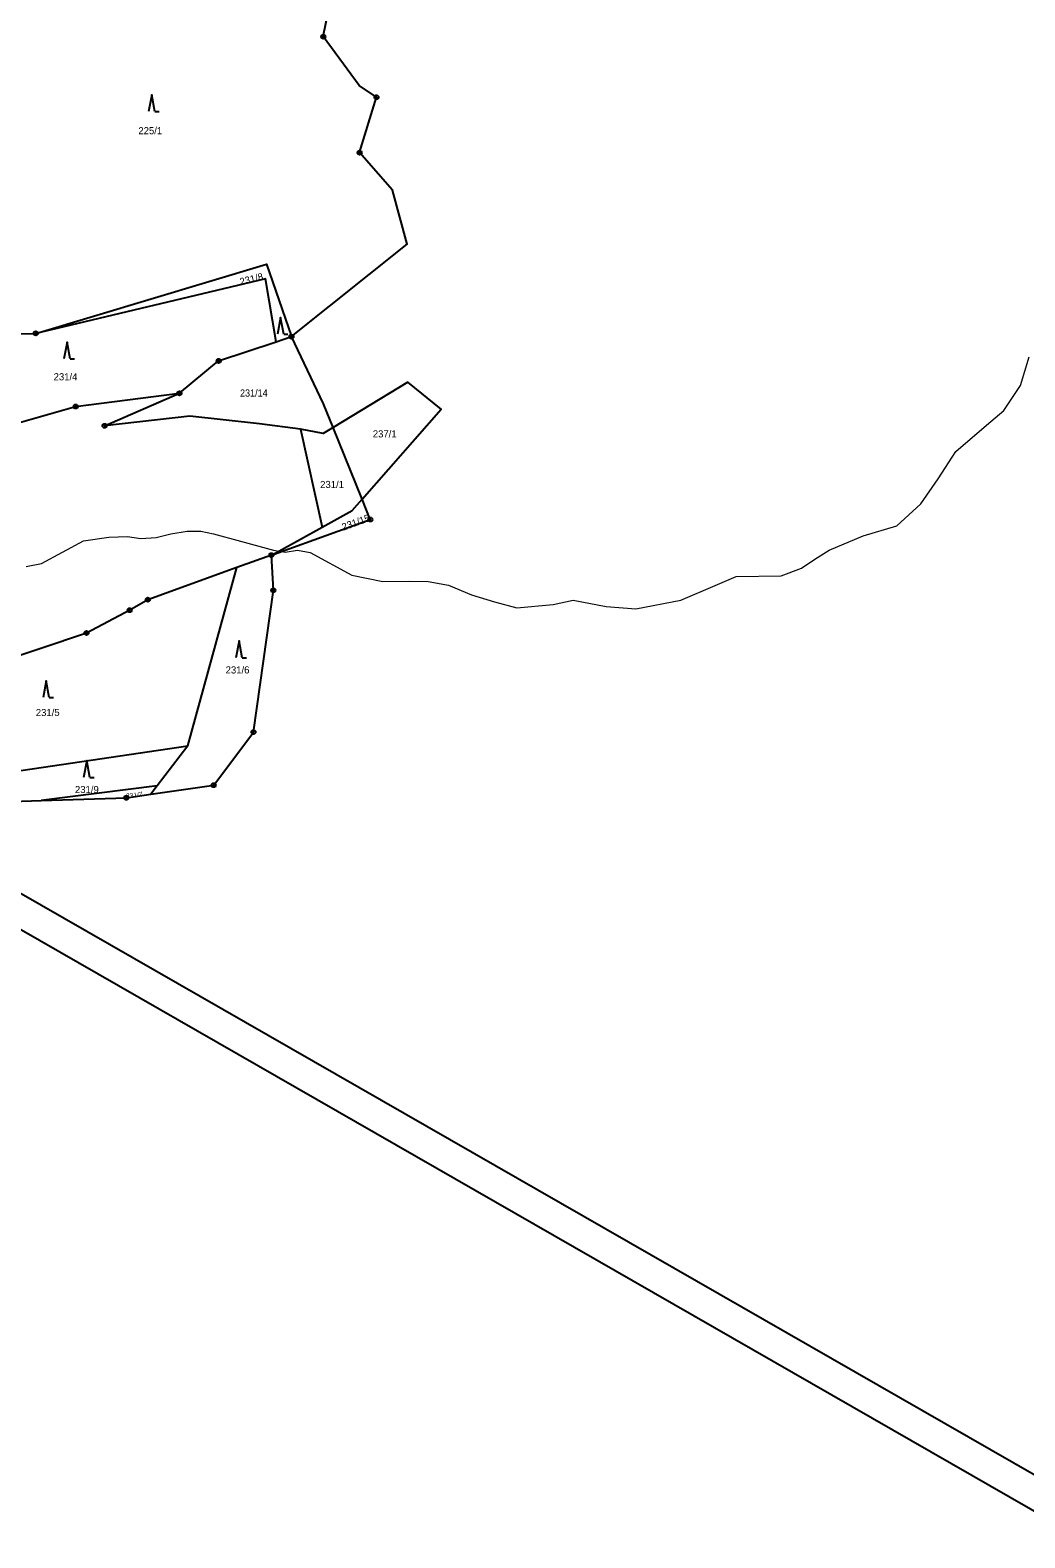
# Model space of a CAD drawing. Extents: x -632162 to -629607, y -1101195 to -1098670.
# Drawn here: x -630992.8 to -630755.2, y -1100113.2 to -1099752.9 of the extents above; entities that cross this region are included whole.
import ezdxf
from ezdxf.enums import TextEntityAlignment as Align

# ---------------------------------------------------------------- set-up
doc = ezdxf.new("R2010")
doc.units = 0
doc.header["$LTSCALE"] = 0.68
for name, color, linetype, lineweight in [('1', 7, 'Continuous', 25), ('3', 7, 'Continuous', 25), ('4', 7, 'Continuous', 13), ('8', 7, 'Continuous', 25)]:
    doc.layers.add(name, color=color, linetype=linetype, lineweight=lineweight)
doc.layers.add('2', color=7, linetype='Continuous')

msp = doc.modelspace()

# ---------------------------------------------------------------- linework, layer by layer
at = {"layer": '1'}
for p, q in [((-630934.02, -1099827.32), (-630930.38, -1099826.1)), ((-630922.68, -1099842.17), (-630930.38, -1099826.1)), ((-630920.41, -1099847.79), (-630922.68, -1099842.17)), ((-630935.15, -1099878.32), (-630943.43, -1099881.3)), ((-630962.47, -1099933.48), (-630990.18, -1099936.98)), ((-630220.5, -1100403.45), (-631019.63, -1099945.14))]:
    msp.add_line(p, q, dxfattribs=at)
for points in [[(-631573.73, -1099649.04), (-631561.78, -1099657.37), (-631473.19, -1099721.18), (-631427.36, -1099745.46), (-631262.62, -1099810.08), (-631104.85, -1099904.21), (-631080.72, -1099918.6), (-630227.98, -1100408.08)], [(-630930.38, -1099826.1), (-630902.71, -1099804.02), (-630906.25, -1099791.11), (-630914.09, -1099782.13), (-630910.06, -1099768.89), (-630914.18, -1099766.08), (-630922.77, -1099754.42), (-630915.37, -1099718.19)], [(-631084.09, -1099829.53), (-631084.12, -1099825.43), (-630991.45, -1099825.32), (-630936.33, -1099808.78), (-630930.38, -1099826.1)], [(-630934.02, -1099827.32), (-630936.54, -1099812.27), (-630991.45, -1099825.32)], [(-631031.66, -1099828.74), (-630998.12, -1099847.45), (-630981.93, -1099842.81), (-630957.14, -1099839.65), (-630947.77, -1099831.91), (-630934.02, -1099827.32)], [(-630928.24, -1099848.23), (-630938.04, -1099846.95), (-630954.65, -1099845.13), (-630975.03, -1099847.41), (-630957.14, -1099839.65)], [(-630913.5, -1099864.92), (-630894.64, -1099843.41), (-630902.6, -1099836.95), (-630920.41, -1099847.79)], [(-630920.41, -1099847.79), (-630922.77, -1099849.25), (-630928.24, -1099848.23), (-630923.05, -1099871.61)], [(-630923.05, -1099871.61), (-630915.89, -1099867.64), (-630913.5, -1099864.92), (-630920.41, -1099847.79)], [(-630935.15, -1099878.32), (-630932.75, -1099877.46), (-630911.53, -1099869.82), (-630913.5, -1099864.92)], [(-630935.15, -1099878.32), (-630933.39, -1099877.35), (-630923.05, -1099871.61)], [(-630948.94, -1099933.3), (-630939.44, -1099920.62), (-630934.7, -1099886.73), (-630935.15, -1099878.32)], [(-631040.6, -1099932.89), (-631035.61, -1099935.8), (-631015.53, -1099932.83), (-630955.16, -1099923.88), (-630943.43, -1099881.3), (-630964.68, -1099888.97)], [(-630964.68, -1099888.97), (-630969.01, -1099891.48), (-630979.34, -1099896.94), (-631001.73, -1099904.44), (-631021.83, -1099906.52), (-631029.86, -1099908.89)], [(-630955.16, -1099923.88), (-630962.47, -1099933.48), (-630963.94, -1099935.46), (-630948.94, -1099933.3)], [(-631015.53, -1099932.83), (-630999.45, -1099937.29), (-630990.18, -1099936.98)], [(-630990.18, -1099936.98), (-630969.81, -1099936.31), (-630963.94, -1099935.46)]]:
    msp.add_lwpolyline(points, dxfattribs=at)
at = {"layer": '3'}
for p, q in [((-630963, -1099772.34), (-630962.004, -1099772.34)), ((-630932.23, -1099825.51), (-630931.234, -1099825.51)), ((-630983.22, -1099831.45), (-630982.224, -1099831.45)), ((-630942.14, -1099902.84), (-630941.144, -1099902.84)), ((-630988.22, -1099912.38), (-630987.224, -1099912.38)), ((-630978.52, -1099931.43), (-630977.524, -1099931.43))]:
    msp.add_line(p, q, dxfattribs=at)
for points in [[(-630963, -1099772.34), (-630963.75, -1099768.34), (-630964.5, -1099772.34)], [(-630932.23, -1099825.51), (-630932.98, -1099821.51), (-630933.73, -1099825.51)], [(-630983.22, -1099831.45), (-630983.97, -1099827.45), (-630984.72, -1099831.45)], [(-630942.14, -1099902.84), (-630942.89, -1099898.84), (-630943.64, -1099902.84)], [(-630988.22, -1099912.38), (-630988.97, -1099908.38), (-630989.72, -1099912.38)], [(-630978.52, -1099931.43), (-630979.27, -1099927.43), (-630980.02, -1099931.43)]]:
    msp.add_lwpolyline(points, dxfattribs=at)
at = {"layer": '4'}
for p, q in [((-630756.23, -1099837.76), (-630754.13, -1099830.91)), ((-630760.17, -1099843.75), (-630756.23, -1099837.76)), ((-630764.33, -1099847.29), (-630760.17, -1099843.75)), ((-630771.68, -1099853.52), (-630764.33, -1099847.29)), ((-630775.91, -1099860.08), (-630771.68, -1099853.52)), ((-630779.98, -1099866.05), (-630775.91, -1099860.08)), ((-630785.71, -1099871.32), (-630779.98, -1099866.05)), ((-630793.8, -1099873.7), (-630785.71, -1099871.32)), ((-630990.11, -1099880.31), (-630980.08, -1099874.88)), ((-630980.08, -1099874.88), (-630974, -1099874.05)), ((-630974, -1099874.05), (-630969.58, -1099873.87)), ((-630969.58, -1099873.87), (-630966.36, -1099874.33)), ((-630966.36, -1099874.33), (-630962.68, -1099874.14)), ((-630962.68, -1099874.14), (-630959.18, -1099873.22)), ((-630959.18, -1099873.22), (-630955.32, -1099872.58)), ((-630955.32, -1099872.58), (-630952, -1099872.58)), ((-630952, -1099872.58), (-630948.97, -1099873.22)), ((-630948.97, -1099873.22), (-630942.52, -1099874.97)), ((-630942.52, -1099874.97), (-630934.69, -1099877.13)), ((-630801.92, -1099877.11), (-630793.8, -1099873.7)), ((-630934.69, -1099877.13), (-630933.39, -1099877.35)), ((-630933.39, -1099877.35), (-630932.75, -1099877.46)), ((-630932.75, -1099877.46), (-630931.87, -1099877.6)), ((-630931.87, -1099877.6), (-630928.96, -1099877.13)), ((-630928.96, -1099877.13), (-630925.89, -1099877.72)), ((-630925.89, -1099877.72), (-630915.92, -1099883.14)), ((-630808.55, -1099881.4), (-630805.32, -1099879.31)), ((-630805.32, -1099879.31), (-630801.92, -1099877.11)), ((-630993.79, -1099881.05), (-630990.11, -1099880.31)), ((-630813.39, -1099883.3), (-630808.55, -1099881.4)), ((-630915.92, -1099883.14), (-630908.58, -1099884.6)), ((-630908.58, -1099884.6), (-630902.27, -1099884.56)), ((-630902.27, -1099884.56), (-630897.68, -1099884.66)), ((-630897.68, -1099884.66), (-630892.85, -1099885.46)), ((-630892.85, -1099885.46), (-630887.35, -1099887.81)), ((-630837.38, -1099889.08), (-630829.15, -1099885.58)), ((-630829.15, -1099885.58), (-630824.13, -1099883.44)), ((-630824.13, -1099883.44), (-630813.39, -1099883.3)), ((-630887.35, -1099887.81), (-630881.86, -1099889.51)), ((-630881.86, -1099889.51), (-630876.53, -1099890.88)), ((-630876.53, -1099890.88), (-630867.89, -1099890.1)), ((-630867.89, -1099890.1), (-630863.05, -1099889.05)), ((-630863.05, -1099889.05), (-630855.21, -1099890.6)), ((-630848.11, -1099891.13), (-630837.38, -1099889.08)), ((-630855.21, -1099890.6), (-630848.11, -1099891.13))]:
    msp.add_line(p, q, dxfattribs=at)
at = {"layer": '8'}
for centre, radius in [((-630922.77, -1099754.4199), 0.5), ((-630922.77, -1099754.4199), 0.0303), ((-630910.06, -1099768.8899), 0.5), ((-630910.06, -1099768.8899), 0.0303), ((-630914.09, -1099782.1299), 0.5), ((-630914.09, -1099782.1299), 0.0303), ((-630991.45, -1099825.3199), 0.5), ((-630991.45, -1099825.3199), 0.0303), ((-630930.38, -1099826.0999), 0.5), ((-630930.38, -1099826.0999), 0.0303), ((-630947.77, -1099831.9099), 0.5), ((-630947.77, -1099831.9099), 0.0303), ((-630957.14, -1099839.6499), 0.5), ((-630957.14, -1099839.6499), 0.0303), ((-630981.93, -1099842.8099), 0.5), ((-630981.93, -1099842.8099), 0.0303), ((-630975.03, -1099847.4099), 0.5), ((-630975.03, -1099847.4099), 0.0303), ((-630911.53, -1099869.8199), 0.5), ((-630911.53, -1099869.8199), 0.0303), ((-630935.15, -1099878.3199), 0.5), ((-630935.15, -1099878.3199), 0.0303), ((-630934.7, -1099886.7299), 0.5), ((-630964.68, -1099888.9699), 0.5), ((-630964.68, -1099888.9699), 0.0303), ((-630934.7, -1099886.7299), 0.0303), ((-630969.01, -1099891.4799), 0.5), ((-630969.01, -1099891.4799), 0.0303), ((-630979.34, -1099896.9399), 0.5), ((-630979.34, -1099896.9399), 0.0303), ((-630939.44, -1099920.6199), 0.5), ((-630939.44, -1099920.6199), 0.0303), ((-630948.94, -1099933.2999), 0.5), ((-630948.94, -1099933.2999), 0.0303), ((-630969.81, -1099936.3099), 0.5), ((-630969.81, -1099936.3099), 0.0303)]:
    msp.add_circle(centre, radius, dxfattribs=at)

# ---------------------------------------------------------------- texts
at = {"layer": '2'}
for s, p in [('225/1', (-630964.1, -1099777.74)), ('231/4', (-630984.35, -1099836.55)), ('237/1', (-630908.09, -1099850.19)), ('231/1', (-630920.67, -1099862.28)), ('231/6', (-630943.25, -1099906.6)), ('231/5', (-630988.6, -1099916.78)), ('231/9', (-630979.25, -1099935.18))]:
    msp.add_text(s, height=1.7, dxfattribs=at).set_placement(p, align=Align.CENTER)
for s, height, rotation, p in [('231/8', 1.7, 14, (-630939.7466, -1099813.1798)), ('231/15', 1.7, 20, (-630914.7147, -1099871.2978)), ('231/7', 1.14, 7, (-630967.844, -1099936.2197))]:
    msp.add_text(s, height=height, rotation=rotation, dxfattribs=at).set_placement(p, align=Align.CENTER)
at = {"layer": '2', "width": 0.95}
msp.add_text('231/14', height=1.7, dxfattribs=at).set_placement((-630939.359, -1099840.43), align=Align.CENTER)

doc.saveas('drawing.dxf')
